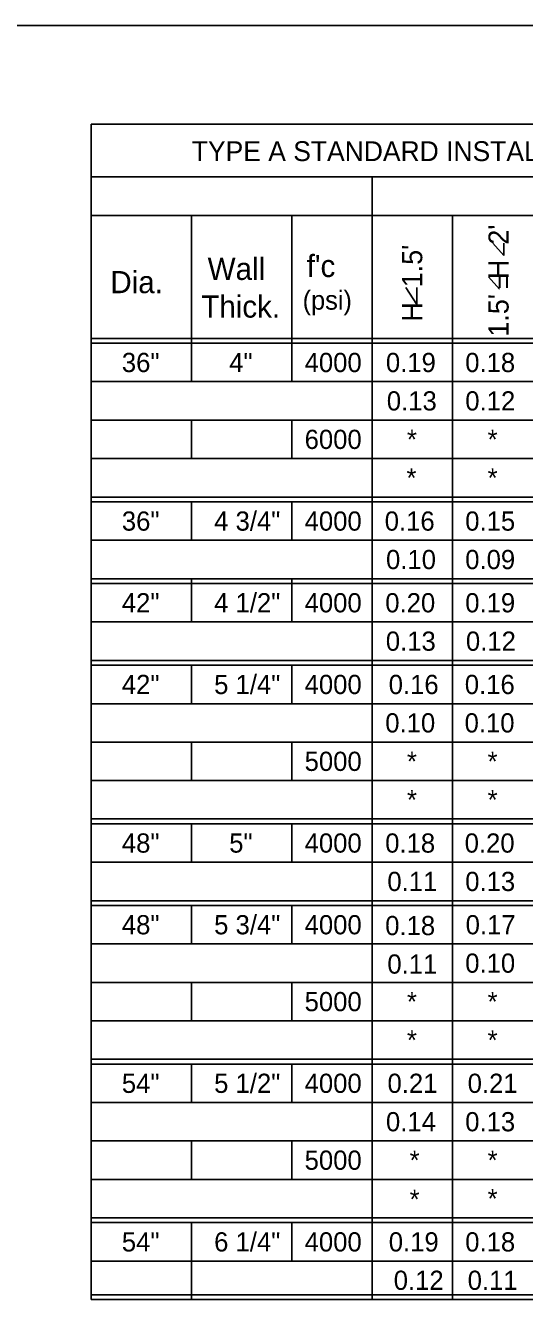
# Model space of a CAD drawing. Extents: x -22562 to -18409, y 3991 to 7171.
# Drawn here: x -20148.1 to -20076.6, y 6169.9 to 6352.4 of the extents above; entities that cross this region are included whole.
import ezdxf

# ---------------------------------------------------------------- set-up
doc = ezdxf.new("R2010")
doc.units = 0
for name, color, linetype in [('1', 7, 'Continuous'), ('2', 7, 'Continuous'), ('3', 7, 'Continuous'), ('4', 7, 'Continuous')]:
    doc.layers.add(name, color=color, linetype=linetype)

msp = doc.modelspace()

# ---------------------------------------------------------------- linework, layer by layer
at = {"layer": '1'}
for p, q in [((-20079.53, 6319.42), (-20081.09, 6321.19)), ((-20079.53, 6319.42), (-20079.53, 6321.18)), ((-20092.01, 6312.42), (-20093.58, 6314.85)), ((-20080.18, 6314.62), (-20081.75, 6316.38)), ((-20092.01, 6312.42), (-20092.01, 6314.83))]:
    msp.add_line(p, q, dxfattribs=at)
at = {"layer": '2'}
for p, q in [((-20344.85, 6352.37), (-19558.85, 6352.37)), ((-20138.7, 6338.24), (-20138.7, 6169.92)), ((-19970.6, 6338.24), (-20138.7, 6338.24)), ((-19970.6, 6330.67), (-20138.7, 6330.67)), ((-20098.41, 6330.67), (-20098.41, 6169.92)), ((-19971.79, 6325.17), (-20138.7, 6325.17)), ((-20124.31, 6325.17), (-20124.31, 6301.36)), ((-20109.92, 6325.17), (-20109.92, 6301.36)), ((-20086.9, 6325.17), (-20086.9, 6169.92)), ((-20138.7, 6307.55), (-19971.79, 6307.55)), ((-20138.7, 6306.86), (-19971.79, 6306.86)), ((-20138.7, 6301.36), (-19971.79, 6301.36)), ((-20138.7, 6295.85), (-19971.79, 6295.85)), ((-20124.31, 6295.85), (-20124.31, 6290.34)), ((-20109.92, 6295.85), (-20109.92, 6290.34)), ((-20138.7, 6290.34), (-19971.79, 6290.34)), ((-20138.7, 6284.84), (-19971.79, 6284.84)), ((-20138.7, 6284.84), (-19971.79, 6284.84)), ((-20138.7, 6284.15), (-19971.79, 6284.15)), ((-20124.31, 6284.15), (-20124.31, 6278.64)), ((-20109.92, 6284.15), (-20109.92, 6278.64)), ((-20138.7, 6278.64), (-19971.79, 6278.64)), ((-20138.7, 6273.14), (-19971.79, 6273.14)), ((-20138.7, 6273.14), (-19971.79, 6273.14)), ((-20124.31, 6273.14), (-20124.31, 6266.95)), ((-20109.92, 6273.14), (-20109.92, 6266.95)), ((-20138.7, 6272.45), (-19971.79, 6272.45)), ((-20138.7, 6266.95), (-19971.79, 6266.95)), ((-20138.7, 6261.44), (-19971.79, 6261.44)), ((-20138.7, 6261.44), (-19971.79, 6261.44)), ((-20138.7, 6260.75), (-19971.79, 6260.75)), ((-20124.31, 6260.75), (-20124.31, 6255.24)), ((-20109.92, 6260.75), (-20109.92, 6255.24)), ((-20138.7, 6255.24), (-19971.79, 6255.24)), ((-20138.7, 6249.74), (-19971.79, 6249.74)), ((-20124.31, 6249.74), (-20124.31, 6244.23)), ((-20109.92, 6249.74), (-20109.92, 6244.23)), ((-20138.7, 6244.23), (-19971.79, 6244.23)), ((-20138.7, 6244.23), (-19971.79, 6244.23)), ((-20138.7, 6238.73), (-19971.79, 6238.73)), ((-20138.7, 6238.04), (-19971.79, 6238.04)), ((-20124.31, 6238.04), (-20124.31, 6232.53)), ((-20109.92, 6238.04), (-20109.92, 6232.53)), ((-20138.7, 6232.53), (-19971.79, 6232.53)), ((-20138.7, 6227.03), (-19971.79, 6227.03)), ((-20138.7, 6226.34), (-19971.79, 6226.34)), ((-20124.31, 6226.34), (-20124.31, 6220.83)), ((-20109.92, 6226.34), (-20109.92, 6220.83)), ((-20138.7, 6220.83), (-19971.79, 6220.83)), ((-20138.7, 6215.33), (-19971.79, 6215.33)), ((-20124.31, 6215.33), (-20124.31, 6209.82)), ((-20109.92, 6215.33), (-20109.92, 6209.82)), ((-20138.7, 6209.82), (-19971.79, 6209.82)), ((-20138.7, 6204.32), (-19971.79, 6204.32)), ((-20138.7, 6203.63), (-19971.79, 6203.63)), ((-20124.31, 6203.63), (-20124.31, 6198.13)), ((-20109.92, 6203.63), (-20109.92, 6198.13)), ((-20138.7, 6198.13), (-19971.79, 6198.13)), ((-20138.7, 6192.62), (-19971.79, 6192.62)), ((-20124.31, 6192.62), (-20124.31, 6187.11)), ((-20109.92, 6192.62), (-20109.92, 6187.11)), ((-20138.7, 6187.11), (-19971.79, 6187.11)), ((-20138.7, 6181.61), (-19971.79, 6181.61)), ((-20138.7, 6181.61), (-19971.79, 6181.61)), ((-20138.7, 6180.92), (-19971.79, 6180.92)), ((-20124.31, 6180.92), (-20124.31, 6175.41)), ((-20109.92, 6180.92), (-20109.92, 6175.41)), ((-20138.7, 6175.42), (-19971.79, 6175.42)), ((-20124.31, 6175.42), (-20124.31, 6169.91)), ((-20138.7, 6170.6), (-19971.79, 6170.6)), ((-20138.7, 6169.92), (-19970.6, 6169.92)), ((-20138.7, 6169.91), (-19971.79, 6169.91)), ((-20138.7, 6169.91), (-19971.79, 6169.91))]:
    msp.add_line(p, q, dxfattribs=at)

# ---------------------------------------------------------------- texts
at = {"layer": '1'}
for s, height, p in [("f'c", 3.172, (-20107.8, 6316.34)), ('Thick.', 3.172, (-20122.91, 6310.53)), ('(psi)', 2.719, (-20108.38, 6311.67)), ('36"', 2.751, (-20134.29, 6302.73)), ('36"', 2.751, (-20134.29, 6280.02)), ('42"', 2.751, (-20134.29, 6268.32)), ('42"', 2.751, (-20134.29, 6256.62)), ('48"', 2.751, (-20134.29, 6233.91)), ('48"', 2.751, (-20134.29, 6222.21)), ('54"', 2.751, (-20134.29, 6199.5)), ('54"', 2.751, (-20134.29, 6176.79))]:
    msp.add_text(s, height=height, dxfattribs=at).set_placement(p)
msp.add_text('=', height=2.88, rotation=90, dxfattribs=at).set_placement((-20078.24, 6314.59))
at = {"layer": '2'}
msp.add_text('TYPE A STANDARD INSTALLATION - STEEL AREAS (in. /ft.)', height=2.8357, dxfattribs=at).set_placement((-20124.26, 6332.95))
at = {"layer": '3'}
for s, height, p in [('0.19', 2.751, (-20096.44, 6302.73)), ('0.18', 2.751, (-20085.07, 6302.73)), ('0.13', 2.751, (-20096.31, 6297.23)), ('0.12', 2.751, (-20085.06, 6297.23)), ('*', 2.75, (-20093.42, 6291.72)), ('*', 2.75, (-20081.86, 6291.72)), ('*', 2.75, (-20093.49, 6286.21)), ('*', 2.75, (-20081.86, 6286.21)), ('0.16', 2.751, (-20096.61, 6280.02)), ('0.15', 2.751, (-20085.07, 6280.02)), ('0.10', 2.751, (-20096.42, 6274.51)), ('0.09', 2.751, (-20085.07, 6274.51)), ('0.20', 2.751, (-20096.53, 6268.32)), ('0.19', 2.751, (-20085.07, 6268.32)), ('0.13', 2.751, (-20096.45, 6262.82)), ('0.12', 2.751, (-20084.97, 6262.82)), ('0.16', 2.751, (-20096.04, 6256.62)), ('0.16', 2.751, (-20085.13, 6256.62)), ('0.10', 2.751, (-20096.53, 6251.12)), ('0.10', 2.751, (-20085.16, 6251.12)), ('*', 2.75, (-20093.42, 6245.61)), ('*', 2.75, (-20081.86, 6245.61)), ('*', 2.75, (-20093.42, 6240.11)), ('*', 2.75, (-20081.86, 6240.11)), ('0.18', 2.751, (-20096.54, 6233.91)), ('0.20', 2.751, (-20085.15, 6233.91)), ('0.11', 2.751, (-20096.23, 6228.41)), ('0.13', 2.751, (-20085.07, 6228.41)), ('0.18', 2.751, (-20096.54, 6222.09)), ('0.17', 2.751, (-20085.01, 6222.21)), ('0.11', 2.751, (-20096.23, 6216.58)), ('0.10', 2.751, (-20085.07, 6216.71)), ('*', 2.75, (-20093.42, 6211.2)), ('*', 2.75, (-20081.86, 6211.2)), ('*', 2.75, (-20093.42, 6205.7)), ('*', 2.75, (-20081.86, 6205.7)), ('0.21', 2.751, (-20096.21, 6199.5)), ('0.21', 2.751, (-20084.72, 6199.5)), ('0.14', 2.751, (-20096.43, 6194)), ('0.13', 2.751, (-20085.07, 6194)), ('*', 2.75, (-20093.04, 6188.49)), ('*', 2.75, (-20081.86, 6188.49)), ('*', 2.75, (-20093.04, 6182.9)), ('*', 2.75, (-20081.86, 6182.99)), ('0.19', 2.752, (-20096.03, 6176.79)), ('0.18', 2.751, (-20085.07, 6176.79)), ('0.12', 2.751, (-20095.32, 6171.29)), ('0.11', 2.751, (-20084.72, 6171.29))]:
    msp.add_text(s, height=height, dxfattribs=at).set_placement(p)
at = {"layer": '4'}
for s, height, p in [("1.5'  H  2'", 2.8834, (-20078.85, 6307.81)), ("H  1.5'", 2.883, (-20091.23, 6309.95))]:
    msp.add_text(s, height=height, rotation=90, dxfattribs=at).set_placement(p)
for s, height, p in [('Wall', 3.172, (-20121.99, 6315.93)), ('Dia.', 3.172, (-20135.94, 6314.03)), ('4"', 2.751, (-20118.9, 6302.73)), ('4000', 2.751, (-20108.09, 6302.73)), ('6000', 2.751, (-20108.09, 6291.72)), ('4 3/4"', 2.751, (-20121.06, 6280.02)), ('4000', 2.751, (-20108.09, 6280.02)), ('4 1/2"', 2.751, (-20121.06, 6268.32)), ('4000', 2.751, (-20108.09, 6268.32)), ('5 1/4"', 2.751, (-20121.06, 6256.62)), ('4000', 2.751, (-20108.09, 6256.62)), ('5000', 2.751, (-20108.09, 6245.61)), ('5"', 2.751, (-20118.9, 6233.91)), ('4000', 2.751, (-20108.09, 6233.91)), ('5 3/4"', 2.751, (-20121.06, 6222.21)), ('4000', 2.751, (-20108.09, 6222.21)), ('5000', 2.751, (-20108.09, 6211.2)), ('5 1/2"', 2.751, (-20121.06, 6199.5)), ('4000', 2.751, (-20108.09, 6199.5)), ('5000', 2.751, (-20108.09, 6188.49)), ('6 1/4"', 2.751, (-20121.06, 6176.79)), ('4000', 2.751, (-20108.09, 6176.79))]:
    msp.add_text(s, height=height, dxfattribs=at).set_placement(p)

doc.saveas('drawing.dxf')
